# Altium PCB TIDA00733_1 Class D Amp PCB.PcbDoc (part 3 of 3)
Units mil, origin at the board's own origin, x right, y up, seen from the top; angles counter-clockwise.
Board outline 5700 x 4500 mil, 4 copper layers (Top Layer, Signal Layer 1, Signal Layer 2, Bottom Layer), stack 61.668 mil thick; 305 components, 186 nets, 894 pads, 1056 vias.
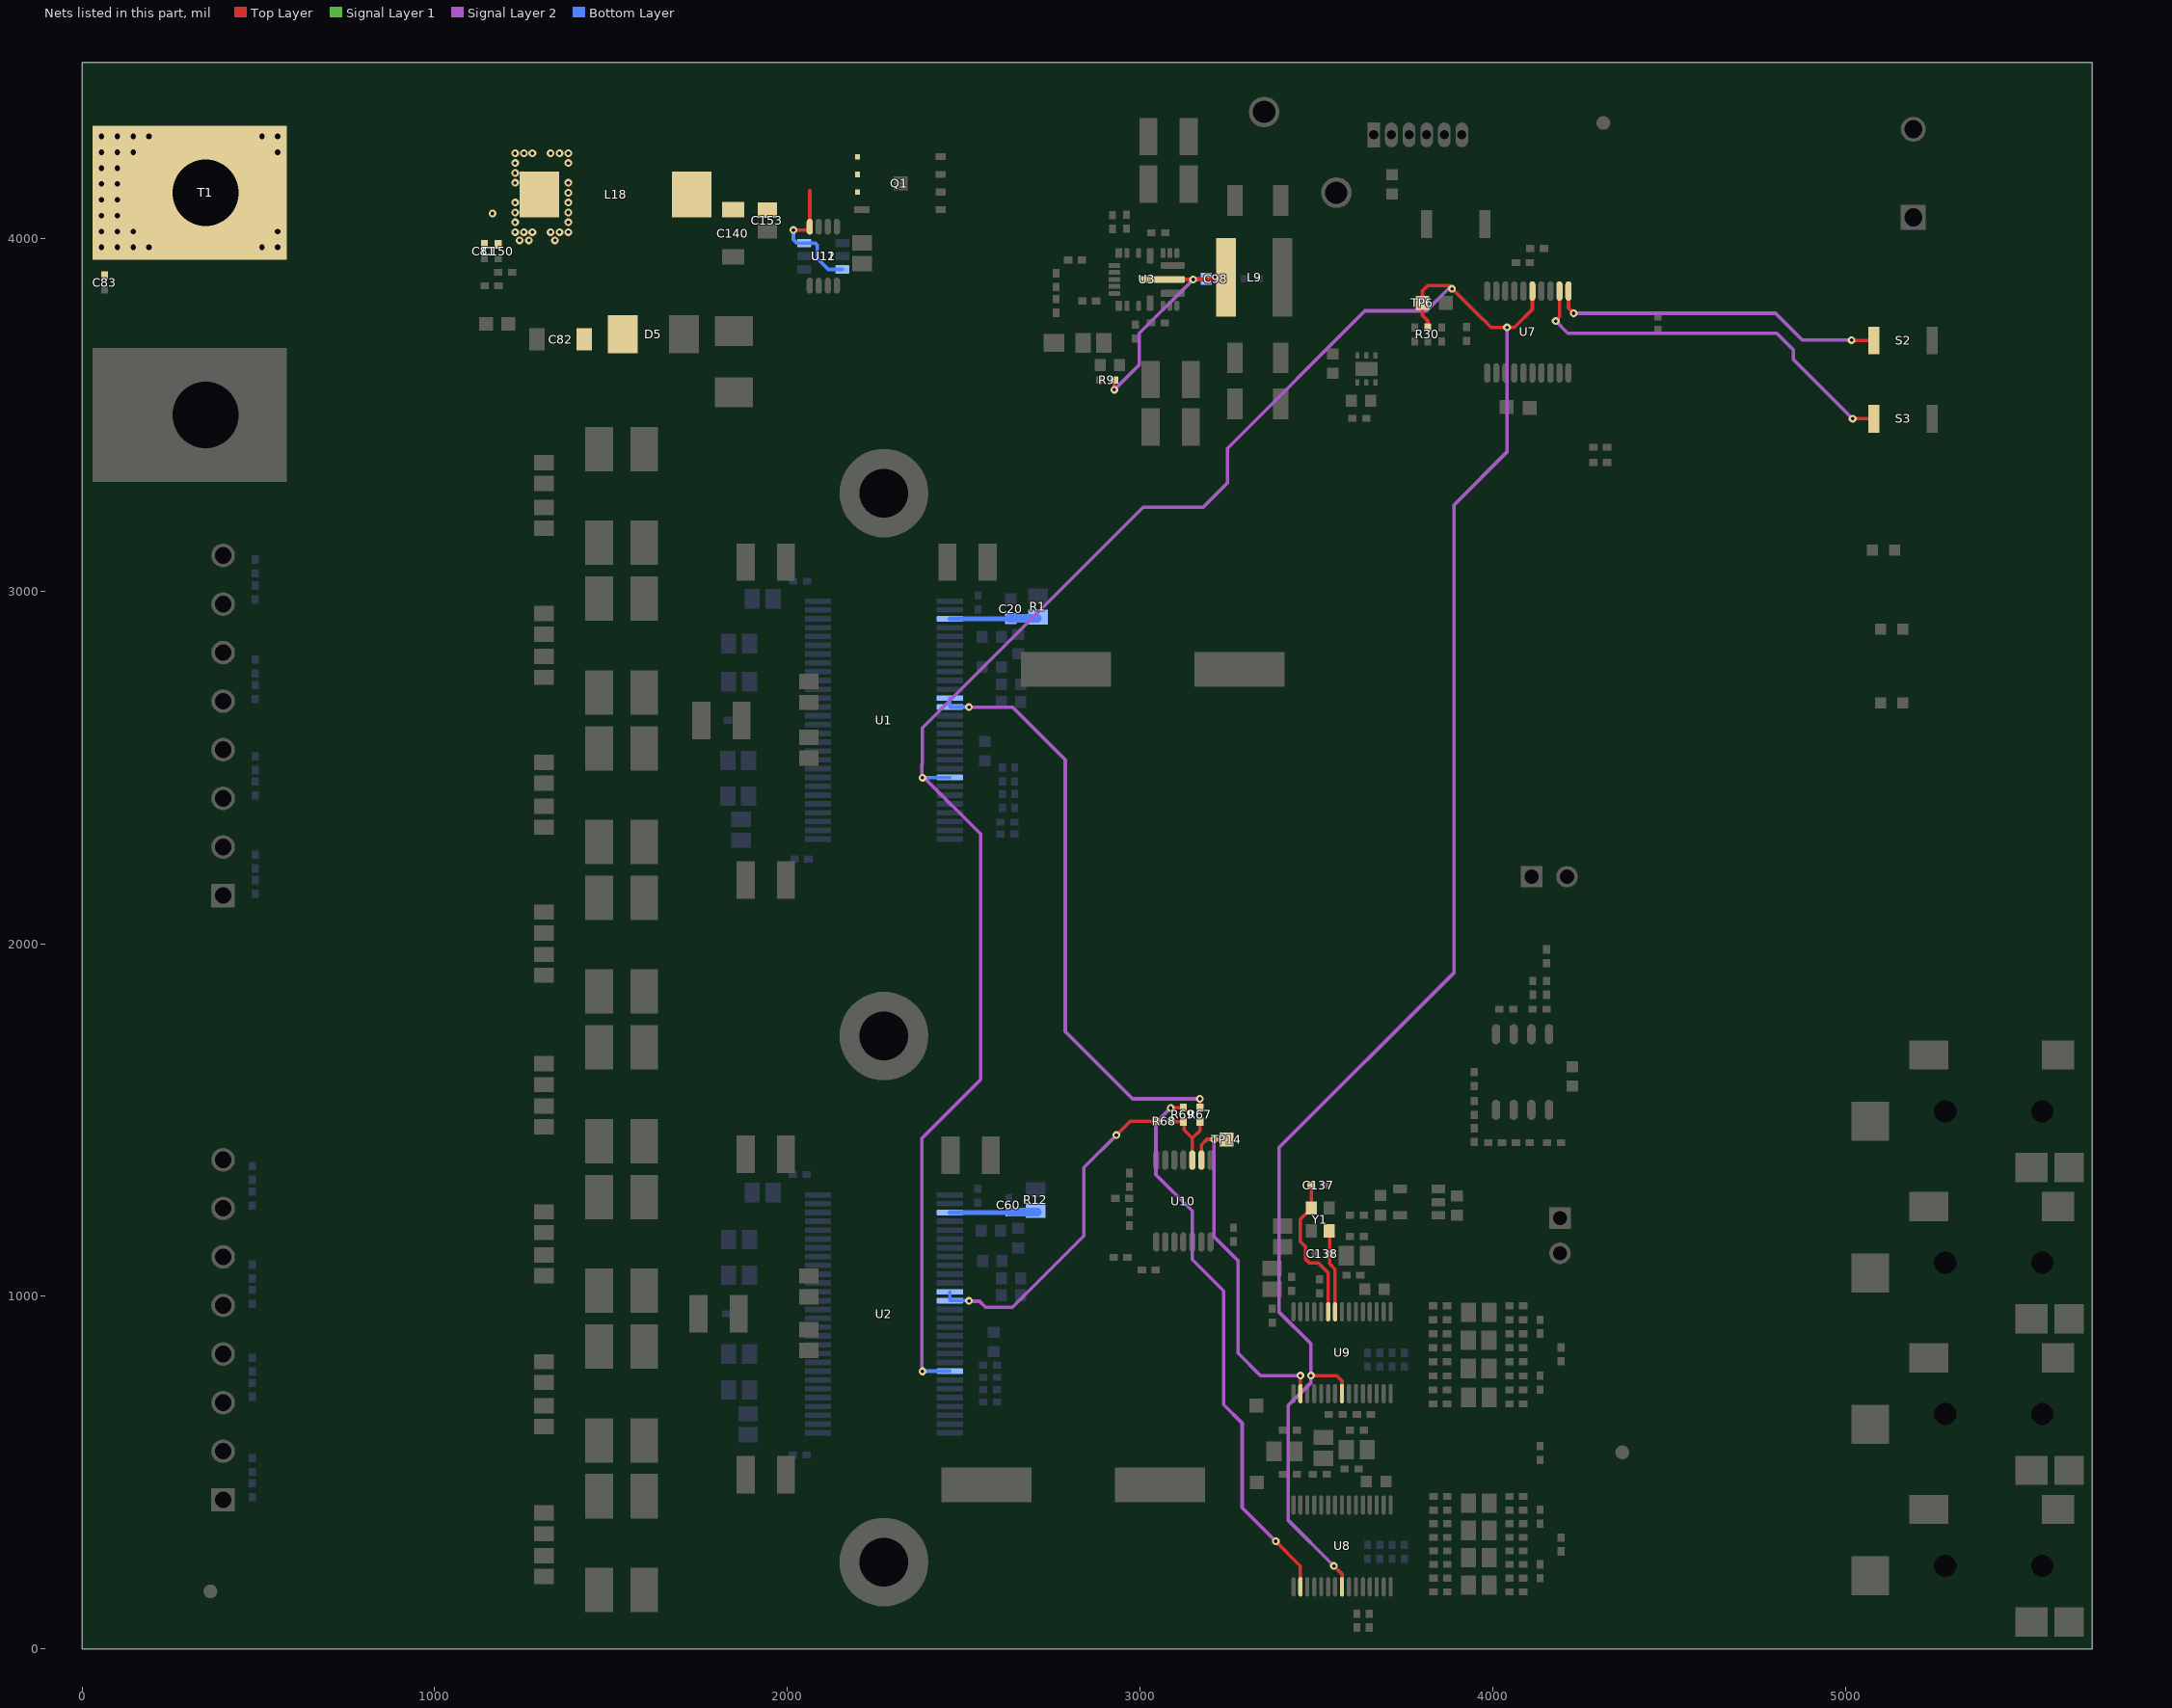
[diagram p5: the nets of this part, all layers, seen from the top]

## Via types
v1: diameter 22, hole 10, Top Layer to Bottom Layer, tented both sides, 975 vias
v2: diameter 32, hole 16, Top Layer to Bottom Layer, tented both sides, 56 vias
v3: diameter 39.37, hole 19.68, Top Layer to Bottom Layer, tented both sides, 18 vias
v4: diameter 26, hole 10, Top Layer to Bottom Layer, 3 vias
v5: diameter 19.68, hole 7.87, Top Layer to Bottom Layer, tented both sides, 2 vias
v6: diameter 26, hole 10, Top Layer to Bottom Layer, tented both sides, 2 vias

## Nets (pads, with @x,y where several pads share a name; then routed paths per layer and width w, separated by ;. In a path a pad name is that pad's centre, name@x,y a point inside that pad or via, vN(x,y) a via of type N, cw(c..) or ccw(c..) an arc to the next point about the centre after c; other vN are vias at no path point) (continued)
SCLK: TP14.1 U9.17 U10.2 | length 999.3
  Top Layer w10: U10.2@3174.18,1386.14 3174.18,1429.18 3190,1445 v1(3210,1445) TP14.1@3235,1445 ; U9.17@3454.89,723.86 3454.89,774.89 v1(3455,775)
  Signal Layer 2 w10: v1(3210,1445) 3210,1169 3278,1101 3278,839 3342,775 v1(3455,775)
SCLK_B1: R67.1 R68.1 R69.1 U10.3 | length 215
  Top Layer w10: R68.1@3084.69,1495 3085,1495.32 3125,1495.32 3125,1472.18 3148.59,1448.59 ; U10.3@3148.59,1386.14 3148.59,1448.59 ; R67.1@3170,1495.32 3170,1470 3148.59,1448.59
SCLK_P2: R69.2 U8.17 | length 1581.6
  Top Layer w10: v1(3087,1534) 3087.69,1534.69 R69.2@3123,1534.69 ; v1(3385,305) 3454.89,235.11 U8.17@3454.89,175.86
  Signal Layer 2 w10: v1(3087,1534) 3045,1492 3045,1345 3148,1242 3148,1104 3237,1015 3237,693 3290,640 3290,400 v1(3385,305)
SCLK_T1: R67.2 U1.12 U1.13 | length 1671.3
  Top Layer w10: R67.2@3170,1534.69 v1(3170,1560)
  Signal Layer 2 w10: v1(2515,2671) 2639,2671 2788,2522 2788,1751 2979,1560 v1(3170,1560)
  Bottom Layer w10: U1.12@2461.01,2696.5 U1.13@2461.01,2671.5 2513.5,2671.5 2514,2671 v1(2515,2671)
SCLK_T2: R68.2 U2.12 U2.13 | length 953.1
  Top Layer w10: v1(2933,1457) 2972,1496 R68.2@3049.31,1496
  Signal Layer 2 w10: v1(2515,987) 2516.2,985.8 2544.86,985.8 2561.86,968.8 2638.8,968.8 2841,1171 2841,1365 v1(2933,1457)
  Bottom Layer w10: U2.12@2461.01,1012.5 U2.13@2461.01,987.5 2514.5,987.5 v1(2515,987)
SDA: R30.1 TP6.1 U1.21 U2.21 U7.15 U8.23 U9.23 | length 8844.4
  Top Layer w10: v1(3485,775) 3558,775 3573,760 U9.23@3573,723.86 ; v1(3550,235) 3573,212 U8.23@3573,175.86 ; R30.1@3816,3747.69 3816,3767 3801,3782 TP6.1@3801,3817 3801,3852 3816,3867 3876.17,3867 v1@3885.26,3857.91 ; v1(3884.83,3857.48) 3889.73,3852.59 v1@3890.59,3852.59 ; v1@3888.17,3855 v1@3890.59,3852.59 ; U7.15@4112.8,3851.14 4112.8,3799 4061.8,3748 v1(4041,3748) 3996,3748 3973,3771 3972.17,3771 v1@3890.59,3852.59
  Signal Layer 2 w10: v1(2383,787) 2381.2,788.8 2381.2,1448.2 2548,1615 2548,2311 v1@2390,2469 ; v1(2383,2471) 2381.2,2472.8 2381.2,2508.66 2383,2510.46 2383,2612 3009,3238 3179,3238 3248,3307 3248,3405 3637.8,3794.8 3811.8,3794.8 3874.48,3857.48 v1(3884.83,3857.48) ; v1(3550,235) 3420,365 3420,690 3485,755 v1(3485,775) 3485,865 3394,956 3394,1421 3891,1918 3891,3245 4040.5,3394.5 v1@4040.5,3748
  Bottom Layer w10: v1(2383,787) 2383.5,787.5 U2.21@2461.01,787.5 ; v1(2383,2471) 2383.5,2471.5 U1.21@2461.01,2471.5
SW_5: C98.1 L9.1 R9.2 U3.9 | length 675.2
  Top Layer w10: R9.2@2926.69,3599 2926.69,3571.31 v1(2927.31,3571.31) ; U3.9@3063.29,3884 v1(3150.9,3884) 3238.5,3884 L9.1@3244.5,3890 L9.1@3259,3904.5
  Signal Layer 2 w10: v1(2927.31,3571.31) 2998,3642 2998,3731.1 v1(3150.9,3884)
  Bottom Layer w10: v1(3150.9,3884) 3152.9,3886 C98.1@3187.44,3886
U1_VBAT: C20.1 R1.2 U1.3 | length 249
  Bottom Layer w10: C20.1@2629.06,2921.5 C20.1@2630,2922.44 ; R1.2@2709.03,2922.44 R1.2@2709.47,2922
  Bottom Layer w13: U1.3@2461.01,2921.5 C20.1@2629.06,2921.5
  Bottom Layer w25: C20.1@2630,2922.44 R1.2@2709.03,2922.44
U2_VBAT: C60.1 R12.2 U2.3 | length 249
  Bottom Layer w10: C60.1@2629.06,1237.5 C60.1@2630,1238.44 ; R12.2@2709.03,1238.44 R12.2@2709.47,1238
  Bottom Layer w13: U2.3@2461.01,1237.5 C60.1@2629.06,1237.5
  Bottom Layer w25: C60.1@2630,1238.44 R12.2@2709.03,1238.44
VBAT: C81.1 C82.1 C83.1 C150.1 D5.1 L18.1 T1.1
  other v1: 1241,3995 1267,3995 1341,3995 1228,4018 1252.5,4018 1277,4018 1328.67,4018 1353.83,4018 1379,4018 1228,4046 1379,4046 1164,4071 1228,4074 1379,4074 1228,4102 1379,4102 1379,4130 1228,4158 1379,4158 1228,4186 1228,4214 1379,4214 1228,4242 1253.17,4242 1277,4242 1328.67,4242 1353.83,4242 1379,4242
  other v2: 55,3975 100,3975 145,3975 190,3975 510,3975 555,3975 55,4020 100,4020 145,4020 555,4020 55,4065 100,4065 55,4110 100,4110 55,4155 100,4155 55,4200 100,4200 55,4245 100,4245 145,4245 555,4245 55,4290 100,4290 145,4290 190,4290 510,4290 555,4290
VIN_FLT: C140.1 C153.1 L18.2 Q1.1 Q1.2 Q1.3 U11.4 U12.3 U12.6 | length 376.1
  Top Layer w10: v1(2017,4024) 2053.95,4024 U11.4@2063.61,4033.66 2063.61,4136.39
  Bottom Layer w10: v1(2017,4024) 2017,3997 2026.6,3987.4 U12.3@2047.87,3987.4 2078.6,3987.4 2085,3981 2085,3944 2116.4,3912.6 U12.6@2156.13,3912.6
VOL_DN: S3.1 U7.12 | length 1122.4
  Top Layer w10: v1(4179,3766) 4179,3767 4189.57,3777.57 U7.12@4189.57,3851.14 ; v1(5021,3489) S3.1@5081.32,3489
  Signal Layer 2 w10: v1(4179,3766) 4213.5,3731.5 4805.5,3731.5 4853,3684 4853,3657 v1(5021,3489)
VOL_UP: S2.1 U7.11 | length 960
  Top Layer w10: U7.11@4215.16,3851.14 4215.16,3802.84 v1(4230,3788) ; v1(5018,3712) 5019,3711 S2.1@5081.32,3711
  Signal Layer 2 w10: v1(4230,3788) 4802,3788 4878,3712 v1(5018,3712)
  Signal Layer 1 w10: v1@4230,3780.51 v1(4230,3788)
XI: C137.1 U9.10 Y1.1 | length 419.1
  Top Layer w10: C137.1@3486.32,1315 3486.32,1250.56 3486.4,1250.48 3455,1219.08 3455,1155 3470,1140 3470,1105 3480,1095 3505,1095 3533.63,1066.37 U9.10@3533.63,956.14
XO: C138.1 U9.9 Y1.3 | length 236.7
  Top Layer w10: Y1.3@3535.61,1185.52 3537.69,1183.44 C138.1@3537.69,1120 3537.69,1092.32 3553.31,1076.68 U9.9@3553.31,956.14
pads on no net: FID1.1 FID2.1 FID3.1 J5.1 J5.6 J6.4 J6.5 J6.MH1 J6.MH2 J7.4 J7.5 J7.MH1 J7.MH2 J8.4 J8.5 J8.MH1 J8.MH2 J9.4 J9.5 J9.MH1 J9.MH2 U3.4A U3.4B U3.8A U3.8B U3.9A U3.9B U3.9C U3.9D U3.10A U3.10B U3.14A U3.14B U3.17 U5.4 U6.3 U6.7@3624.28,3630 U6.7@3659.72,3630 U7.2 U7.3 U7.7 U7.10 U7.13 U7.18 U7.19 U8.5 U8.9 U8.10 U8.15 U8.19 U8.20 U8.21 U8.22 U9.5 U9.15 U9.19 U9.20 U9.21 U9.22 U10.11 U11.3 U11.5

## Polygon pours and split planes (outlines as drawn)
PVDD on Top Layer "TOP_LAYER_PVDD_P280" (solid, remove dead copper, pour order 280): 2233,646 2276,603 2363,603 2419,547 2727,547 2727,381 2376,381 2324,433 2151,433 1967,433 1967,528 2051,612 2051,764 2100,813 2100,1123 2014,1210.19 2014,2410.26 2098.56,2494.82 2098.56,2775.18 2014,2859.74 2014,3652.62 2080,3710.97 2489,3710.97 2489,3500 2201,3500 2148,3447 2148,2933 2170,2911 2423,2911 2540,2911 2543,2914 2543,3031 2609,3031 2609,2883 2630,2862 2918,2862 2918,2696 2401,2696 2307,2602 2307,2423 2151,2267 2151,2126 2151,1381 2188,1344 2596,1344 2596,1341 2612,1325 2610,1323 2610,1243 2604,1237 2295,1237 2289,1237 2233,1181
GND on Top Layer "Top GND" (solid, remove dead copper, pour order 326): 25,4475 5675,4475 5675,25 25,25
SW_5 on Top Layer "Top Layer-No Net" (solid, remove dead copper, pour order 204): 3066,3894 3121,3894 3131,3904 3151,3924 3151,3939 3151,3959 3186,3994 3196,4004 3216,4004 3271,4004 3271,3779 3211,3779 3196,3779 3161,3814 3151,3824 3151,3844 3141,3854 3121,3874 3111,3874 3066,3874
PVDD on Top Layer "Top Layer-No Net" (solid, remove dead copper, pour order 206): 2272,4243.81 2371.19,4343 2472,4345 3051,4345 3051,3874 3051,3406 2643,3406 2549,3500 2272,3500
VBAT on Top Layer "Top Layer-No Net" (solid, remove dead copper, pour order 205): 1412,4096 1573,3935 1573,3678 1571,3676 1570,3677 1399,3677 1399,3733 1399,3946 1373,3972 1132,3972 1132,4322 1412,4322 1412,4182
PVDD on Top Layer "Top Layer-No Net" (solid, remove dead copper, pour order 200): 1909,1001 1929,981 1944,966 1954,966 1964,966 2110,966 2110,936 1944,936 1909,896 1878,896 1878,1001
PVDD on Top Layer "Top Layer-No Net" (solid, remove dead copper, pour order 259): 1894,2685 1929,2650 1954,2650 1964,2650 2112,2650 2112,2620 1927.75,2620 1892.75,2580 1878,2580 1878,2685
OUT8+ on Signal Layer 1 "SIGNAL_LAYER_1_OUT8+_P284" (solid, remove dead copper, pour order 284): 1204,3472 1004,3472 689,3157 352,3157 352,3032 862,3032 1172,3342 1204,3342 1208,3346 1208,3471
OUTCP on Signal Layer 1 "Top Layer-No Net" (solid, remove dead copper, pour order 225): 1633.58,933.9 1633.58,773.9 1650.3,757.18 1826.87,757.18 1933.58,863.9 1958.58,863.9 1993.58,863.9 1993.58,915.18 1864.87,915.18 1822.87,873.18 1724.3,873.18 1663.58,933.9
OUT3P2 on Signal Layer 1 "Top Layer-No Net" (solid, remove dead copper, pour order 227): 1601,1357 1676,1357 1686,1357 1686,1252 1741,1197 1809.72,1128.28 1889,1128.28 1933,1084.28 1993,1084.28 1993,1037 1946,1037 1796,1037 1726,1037 1631,1132 1601,1162 1601,1182
OUT4P2 on Signal Layer 1 "Top Layer-No Net" (solid, remove dead copper, pour order 231): 1633,1772.74 1633,1642.74 1633,1592.74 1658,1567.74 1693,1532.74 1693,1317.74 1820.72,1190.03 1993,1190.03 1993,1247.74 1988,1252.74 1933,1252.74 1848,1337.74 1815.5,1370.24 1815.5,1410.24 1815.5,1642.74 1688,1772.74
OUTSP on Signal Layer 1 "Top Layer-No Net" (solid, remove dead copper, pour order 229): 1629,361.48 1744.02,361.48 1837.75,455.22 1837.75,534.25 1909,605.5 1909,678.5 1940.72,710.22 1994,710.22 1994,775.22 1954,775.22 1899,775.22 1731,607.22 1731,559.72 1663.39,492.11 1629,492.11
OUT1P on Signal Layer 1 "Top Layer-No Net" (solid, remove dead copper, pour order 228): 1632,2060.5 1667,2060.5 1712,2060.5 1760.75,2060.5 1840.75,2140.5 1840.75,2221.75 1897,2278 1912,2293 1912,2360.5 1947,2395.5 1997,2395.5 1997,2460.5 1957,2460.5 1887,2460.5 1882,2455.5 1822,2395.5 1719.5,2293 1719.5,2278 1719.5,2230.5 1679.5,2190.5 1632,2190.5
OUT4P on Signal Layer 1 "Top Layer-No Net" (solid, remove dead copper, pour order 230): 1638,3464 1638,3334 1638,3284 1663,3259 1698,3224 1698,3009 1833,2874 1998,2874 1998,2939 1993,2944 1938,2944 1853,3029 1820.5,3061.5 1820.5,3101.5 1820.5,3334 1693,3464
OUT3P on Signal Layer 1 "Top Layer-No Net" (solid, remove dead copper, pour order 226): 1603,3042 1678,3042 1688,3042 1688,2937 1743,2882 1808,2817 1893,2817 1908,2817 1933,2792 1943,2792 1963,2792 1998,2792 1998,2722 1948,2722 1798,2722 1728,2722 1633,2817 1603,2847 1603,2867
OUT2P on Signal Layer 1 "Top Layer-No Net" (solid, remove dead copper, pour order 224): 1633,2616 1633,2456 1683,2406 1733,2406 1808,2406 1923,2521 1948,2546 1958,2546 1998,2546 1998,2591 1998,2611 1943,2611 1898,2611 1878,2611 1808,2541 1793,2541 1738,2541 1663,2616
OUT7+ on Signal Layer 1 "SIGNAL_LAYER_1_OUT7+_P286" (solid, remove dead copper, pour order 286): 1208.67,3046.46 978.67,3046.46 808.08,2875.87 353.67,2875.87 353.67,2757.87 1046.87,2757.87 1208.67,2919.67
OUT5+ on Signal Layer 1 "SIGNAL_LAYER_1_OUT5+_P302" (solid, remove dead copper, pour order 302): 1200.23,2065 1200.23,2195 846,2195 703,2338 352,2338 352,2201 571.79,2201 707.8,2065
OUT6+ on Signal Layer 1 "SIGNAL_LAYER_1_OUT6+_P304" (solid, remove dead copper, pour order 304): 351.82,2476.59 351.82,2613 898,2613 905,2620 1200,2620 1200,2490 1186,2476 1159,2449 599.39,2449 571.79,2476.59
OUT2+ on Signal Layer 1 "SIGNAL_LAYER_1_OUT2+_P318" (solid, remove dead copper, pour order 318): 351.82,762.59 351.82,899 898,899 924,925 1200,925 1200,794 1141,735 599.39,735 571.79,762.59
OUT1+ on Signal Layer 1 "SIGNAL_LAYER_1_OUT1+_P320" (solid, remove dead copper, pour order 320): 1200.23,365 1200.23,500 827,500 703,624 352,624 352,487 571.79,487 693.79,365
OUT3+ on Signal Layer 1 "SIGNAL_LAYER_1_OUT3+_P322" (solid, remove dead copper, pour order 322): 1208.67,1345 991.21,1345 808.08,1161.87 353.67,1161.87 353.67,1043.87 1038.87,1043.87 1208.67,1213.67
OUT4+ on Signal Layer 1 "SIGNAL_LAYER_1_OUT4+_P324" (solid, remove dead copper, pour order 324): 1204,1758 1004,1758 689,1443 352,1443 352,1318 862,1318 1172,1628 1204,1628 1208,1632 1208,1757
GND on Signal Layer 1 "Sig 1 GND" (solid, remove dead copper, pour order 334): 25,4475 5675,4475 5675,25 25,25
+5V on Signal Layer 2 "Top Layer-No Net" (solid, remove dead copper, pour order 240): 3429,4200 5245,4200 5245,3990 5245,3963 3429,3963
OUT8- on Signal Layer 2 "SIGNAL_LAYER_2_OUT8-_P282" (solid, remove dead copper, pour order 282): 1206,3072 1206,3200 1202,3204 739,3204 567,3032 353,3032 353,2903 486,2903 732,2903 899,3070 1201,3070
OUTCM on Signal Layer 2 "Top Layer-No Net" (solid, remove dead copper, pour order 210): 1629,666.5 1629,686.5 1629,711.5 1679,761.5 1714,796.5 1779,861.5 1814,861.5 1994,861.5 1994,816.5 1994,801.5 1974,781.5 1869,781.5 1824,736.5 1709,621.5 1709,551.5 1679,521.5 1629,521.5
OUT3M2 on Signal Layer 2 "Top Layer-No Net" (solid, remove dead copper, pour order 208): 1622.71,1066.64 1691.71,1135.64 1816.71,1135.64 1920.71,1031.64 1992.71,1031.64 1992.71,982.64 1854.71,982.64 1811.71,1025.64 1738.71,1025.64 1667.71,954.64 1622.71,954.64
OUT4M2 on Signal Layer 2 "Top Layer-No Net" (solid, remove dead copper, pour order 211): 1633,1517.72 1668,1517.72 1713,1517.72 1798,1432.72 1798,1397.72 1838,1357.72 1903,1292.72 1908,1287.72 1908,1207.72 1929.72,1186 1993,1186 1993,1132 1873.72,1132 1823,1182.72 1823,1197.72 1693,1327.72 1644.72,1376 1633,1376
OUTSM on Signal Layer 2 "Top Layer-No Net" (solid, remove dead copper, pour order 214): 1634,101.89 1634,236 1694,296 1694,349.89 1731.5,387.39 1731.5,611.78 1824.72,705 1994,705 1994,640 1989,635 1934,635 1840,541 1840,268.5 1816.5,245 1673.39,101.89
OUT1M on Signal Layer 2 "Top Layer-No Net" (solid, remove dead copper, pour order 213): 1637,1799 1637,1929 1637,1979 1662,2004 1697,2039 1697,2191.5 1734.5,2229 1734.5,2291.5 1832,2389 1997,2389 1997,2324 1992,2319 1937,2319 1852,2234 1852,2174 1819.5,2141.5 1819.5,1929 1692,1799
OUT4M on Signal Layer 2 "Top Layer-No Net" (solid, remove dead copper, pour order 212): 1638,3202 1673,3202 1718,3202 1803,3117 1803,3082 1843,3042 1908,2977 1913,2972 1913,2892 1938,2867 1998,2867 1998,2802 1963,2802 1893,2802 1888,2807 1828,2867 1828,2882 1698,3012 1698,3037 1668,3067 1638,3067
OUT3M on Signal Layer 2 "Top Layer-No Net" (solid, remove dead copper, pour order 207): 1628,2777.5 1678,2827.5 1693,2827.5 1768,2827.5 1838,2827.5 1848,2817.5 1948,2717.5 1968,2717.5 1998,2717.5 1998,2657.5 1998,2652.5 1943,2652.5 1933,2652.5 1898,2652.5 1873,2677.5 1823,2727.5 1738,2727.5 1723,2712.5 1658,2647.5 1628,2647.5
OUT2M on Signal Layer 2 "Top Layer-No Net" (solid, remove dead copper, pour order 209): 1632,2349.5 1632,2369.5 1632,2394.5 1682,2444.5 1717,2479.5 1782,2544.5 1817,2544.5 1997,2544.5 1997,2499.5 1997,2484.5 1977,2464.5 1872,2464.5 1827,2419.5 1712,2304.5 1712,2234.5 1692,2214.5 1632,2214.5
+3P3V on Signal Layer 2 "SIGNAL_LAYER_2_+3P3V_P278" (solid, remove dead copper, pour order 278): 3813,3376 3910,3473 3910,3581 3910,3725 3749.62,3725 3749.62,3522 3677,3522 3652,3497 3652,3429 3705,3376
OUT7- on Signal Layer 2 "SIGNAL_LAYER_2_OUT7-_P288" (solid, remove dead copper, pour order 288): 1206,2650 1206,2781 591.59,2781 567,2756.41 353,2756.41 353,2627.41 486,2627.41 884.41,2627.41 907,2650
OUT5- on Signal Layer 2 "SIGNAL_LAYER_2_OUT5-_P294" (solid, remove dead copper, pour order 294): 1201.23,1630.77 1200.23,1631.77 1200.23,1928.77 1083.23,1928.77 806,2206 352,2206 352,2071 689,2071 961.23,1798.77 1201.23,1798.77
OUT4- on Signal Layer 2 "SIGNAL_LAYER_2_OUT4-_P296" (solid, remove dead copper, pour order 296): 1206,1375 1206,1508 755,1508 567,1320 353,1320 353,1191 486,1191 732,1191 916,1375
OUT6- on Signal Layer 2 "SIGNAL_LAYER_2_OUT6-_P292" (solid, remove dead copper, pour order 292): 352,2342 352,2478 861,2478 984,2355 1200,2355 1200,2224 1067,2224 831,2224 713,2342
OUT2- on Signal Layer 2 "SIGNAL_LAYER_2_OUT2-_P308" (solid, remove dead copper, pour order 308): 352,628 352,764 861,764 970,655 1200,655 1200,525 806,525 703,628
OUT1- on Signal Layer 2 "SIGNAL_LAYER_2_OUT1-_P310" (solid, remove dead copper, pour order 310): 1200.23,100 1200.23,231 1097,231 836,492 352,492 352,357 701,357 957.27,100
OUT3- on Signal Layer 2 "SIGNAL_LAYER_2_OUT3-_P314" (solid, remove dead copper, pour order 314): 1206,949 1206,1080 604.59,1080 567,1042.41 353,1042.41 353,913.41 486,913.41 884.41,913.41 920,949
GND on Signal Layer 2 "Sig 2 GND" (solid, remove dead copper, pour order 330): 25,4475 5675,4475 5675,25 25,25
OUT1M on Bottom Layer "Top Layer-No Net" (solid, remove dead copper, pour order 276): 2035,2390 1935,2390 1913,2368 1913,2333 1921,2325 1945,2325 1965,2325 1990,2350 2005,2365 2035,2365 2090,2365 2090,2380 2045,2380
OUT1P on Bottom Layer "Top Layer-No Net" (solid, remove dead copper, pour order 274): 2090,2415 2090,2410 2045,2410 2035,2400 2015,2400 1912,2400 1907,2405 1907,2439 1912,2444 1986,2444 2000,2430 2010,2430 2090,2430
OUT2P on Bottom Layer "Top Layer-No Net" (solid, remove dead copper, pour order 272): 2090,2565 2090,2560 2045,2560 2035,2550 1930,2550 1907,2573 1907,2592 1915,2600 1971,2600 1991,2580 2010,2580 2090,2580
OUT2M on Bottom Layer "Top Layer-No Net" (solid, remove dead copper, pour order 270): 2034,2541 1912,2541 1906,2535 1906,2498 1908,2496 1978,2496 1997,2515 2035,2515 2090,2515 2090,2530 2045,2530
GND on Bottom Layer "Bottom Layer GND" (solid, remove dead copper, pour order 332): 25,4475 5675,4475 5675,25 25,25
OUTCM on Bottom Layer "Top Layer-No Net" (solid, remove dead copper, pour order 248): 2034,857 1912,857 1906,851 1906,814 1908,812 1978,812 1997,831 2035,831 2090,831 2090,846 2045,846
OUTCP on Bottom Layer "Top Layer-No Net" (solid, remove dead copper, pour order 256): 2090,881 2090,876 2045,876 2035,866 1930,866 1907,889 1907,908 1915,916 1971,916 1991,896 2010,896 2090,896
OUT3P2 on Bottom Layer "Top Layer-No Net" (solid, remove dead copper, pour order 255): 2090,1056 2090,1051 2045,1051 2031,1037 1899,1037 1899,1087 1984,1087 2000,1071 2010,1071 2090,1071
OUT3M2 on Bottom Layer "Top Layer-No Net" (solid, remove dead copper, pour order 243): 2038,1028 1926,1028 1920,1022 1920,1001 1938,983 1982,983 1990,991 2005,1006 2035,1006 2090,1006 2090,1021 2045,1021
OUT4M2 on Bottom Layer "Top Layer-No Net" (solid, remove dead copper, pour order 250): 2032,1184 1899,1184 1899,1134 1983,1134 1990,1141 2005,1156 2035,1156 2090,1156 2090,1171 2045,1171
OUT4P2 on Bottom Layer "Top Layer-No Net" (solid, remove dead copper, pour order 258): 2090,1206 2090,1201 2045,1201 2039,1195 1942,1195 1894,1243 1894,1277 1922,1277 1922,1258 1937.01,1243 1981,1243 2003,1221 2010,1221 2090,1221
OUTSP on Bottom Layer "Top Layer-No Net" (solid, remove dead copper, pour order 254): 2090,731 2090,726 2045,726 2035,716 2015,716 1912,716 1907,721 1907,755 1912,760 1986,760 2000,746 2010,746 2090,746
OUTSM on Bottom Layer "Top Layer-No Net" (solid, remove dead copper, pour order 244): 2035,706 1935,706 1913,684 1913,649 1921,641 1945,641 1965,641 1990,666 2005,681 2035,681 2090,681 2090,696 2045,696
OUT4P on Bottom Layer "OUT4P" (solid, remove dead copper, pour order 262): 2090,2890 2090,2885 2045,2885 2039,2879 1942,2879 1894,2927 1894,2961 1922,2961 1922,2942 1937.01,2927 1981,2927 2003,2905 2010,2905 2090,2905
OUT4M on Bottom Layer "OUT4M" (solid, remove dead copper, pour order 264): 2032,2868 1899,2868 1899,2818 1983,2818 1990,2825 2005,2840 2035,2840 2090,2840 2090,2855 2045,2855
OUT3M on Bottom Layer "PUT3M" (solid, remove dead copper, pour order 266): 2038,2712 1926,2712 1920,2706 1920,2685 1938,2667 1982,2667 1990,2675 2005,2690 2035,2690 2090,2690 2090,2705 2045,2705
OUT3P on Bottom Layer "OUT3P" (solid, remove dead copper, pour order 268): 2090,2740 2090,2735 2045,2735 2031,2721 1899,2721 1899,2771 1984,2771 2000,2755 2010,2755 2090,2755

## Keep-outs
Keep-Out Layer:
  text ".Layer_Name" at 7,-1458.49 h60

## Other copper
Top Layer:
  rectangle net GND: 2438,1348 2522,1452
  region net AGND: 2771,3732 2771,3677 2854,3677 2854,3732
  rectangle net OUT1-: 1170,100 1505,230
  rectangle net OUT1+: 1170,363 1505,498
  rectangle net OUT2-: 1170,527 1505,657
  rectangle net OUT2+: 1170,792 1505,922
  rectangle net OUT3-: 1170,952 1505,1082
  rectangle net OUT3+: 1170,1215 1505,1345
  rectangle net OUT4-: 1170,1375 1505,1505
  rectangle net OUT4+: 1170,1638 1505,1773
  rectangle net OUT5-: 1170,1803 1505,1933
  rectangle net OUT5+: 1170,2065 1505,2195
  rectangle net OUTSM: 1555,100 1665,235
  rectangle net OUTSP: 1555,365 1665,495
  rectangle net OUTCM: 1555,525 1665,655
  rectangle net OUTCP: 1555,790 1665,920
  rectangle net OUT3M2: 1555,950 1665,1080
  rectangle net OUT3P2: 1555,1212 1665,1347
  rectangle net OUT4M2: 1555,1377 1665,1507
  rectangle net OUT4P2: 1555,1640 1665,1770
  rectangle net OUT1M: 1555,1799 1665,1934
  rectangle net OUT1P: 1555,2060 1665,2195
  rectangle net PVDD: 1970,446 2125,546
  rectangle net PVDD: 2545,1251 2610,1485
  rectangle net PVDD: 1970,1346 2125,1451
  rectangle net OUT8+: 1170,3340 1500,3466
  rectangle net OUT8-: 1170,3072 1505,3202
  region net NetD5_2: 1641,3820 1641,3625 1931,3625 1931,3820
  rectangle net OUT7+: 1170,2912 1505,3042
  rectangle net OUT7-: 1170,2650 1505,2780
  rectangle net OUT6+: 1170,2490 1505,2620
  rectangle net OUT6-: 1170,2225 1505,2355
  rectangle net OUT4P: 1555,3339 1665,3466
  rectangle net OUT4M: 1555,3072 1665,3202
  rectangle net OUT3P: 1555,2906 1665,3041
  rectangle net OUT3M: 1555,2648 1665,2778
  rectangle net OUT2P: 1555,2483 1665,2618
  rectangle net OUT2M: 1555,2224 1665,2359
  rectangle net PVDD: 1970,3030 2125,3135
  rectangle net PVDD: 2545,2935 2610,3165
  rectangle net PVDD: 1970,2128 2125,2234
  region net +5V: 3346,4156 3346,3344 3501,3344 3501,4156
  region net +3P3V: 3707,3500 3632,3500 3632,3475 3707,3475
  region net GND: 2700.86,3734 2700.86,3673.86 2746,3673.86 2746,3734
  rectangle net GND: 2381,3027 2479.31,3134.95
  region net VIN_FLT: 2001,4059 2001,4011 2072,4011 2072,4058 2072,4107.03 2240,4106.98 2240,4272 1993,4272 1992,4271 1668,4271 1668,4059
  pour cut-out: 2951,3829 2951,4049 2886,4049 2811,3974 2811,3934 2779.59,3903.84 2779.59,3725.41 2811,3694 2986,3694 2992.23,3700.23 2992.23,3829.05
  pour cut-out: 2778.76,3857 2779,3663.66 2768.21,3663.66 2712,3663.66 2712,3857
  region net AGND: 2848,3880 2838,3890 2811,3890 2786,3865 2786,3732 2771,3732 2771,3676 2848,3676
  region net VBAT: 213,3882 45,3882 45,3955 211,3955
  text ".Layer_Name" at 7,-1458.49 h60
Signal Layer 2:
  rectangle net +5V: 3435.86,3340 3494,3439.14
  region net VBAT: 30,3940 598,3940 1411,3940 1411,4323 30,4323
  text ".Layer_Name" at 7,-1458.49 h60
Signal Layer 1:
  region net VBAT: 30,3940 598,3940 1411,3940 1411,4323 30,4323
  text ".Layer_Name" at 7,-1458.49 h60
Bottom Layer:
  rectangle net PVDD: 2560,1252 2605,1485
  rectangle net PVDD: 2030,929 2121,971
  rectangle net PVDD: 2560,2936 2609,3165
  rectangle net PVDD: 2040,446 2135,646
  rectangle net PVDD: 2530,1252 2600,1280
  rectangle net PVDD: 2040,1256 2135,1451
  rectangle net PVDD: 2040,2940 2135,3135
  rectangle net PVDD: 2530,2936 2600,2965
  rectangle net PVDD: 2045,2130 2135,2330
  rectangle net PVDD: 2030,2613 2121,2655
  rectangle net +5V: 3434.32,3342 3496,3440.16
  text ".Layer_Name" at 7,-1458.49 h60

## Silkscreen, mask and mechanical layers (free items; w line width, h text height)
Top Overlay:
  lines w10: 1080,0 1080,4500 ; 3797,688 3808,699 ; 4269,1673 4286,1690 4288,1690 4300,1690 ; 4500,0 4500,4500
  text "'.PRJ_Number'  .PCB_Rev-" at 2306,4329 h108.27
  text "POWER INPUT" at 690,4311 h160 r270
  text "-" at 5585,4294 h160 r90
  text "+" at 588,4173 h160 r270
  text "+" at 5604,3999 h160 r90
  text "+5V, 3A OUTPUT" at 5651,3867 h80 r90
  text "SDA" at 3820,3851 h50 r90
  text "SCL" at 3879,3846 h50 r90
  text "-" at 609,3471 h160 r270
  text "+" at 228,3067.77 h160 r90
  text "8" at 148,3047.77 h100 r270
  text "POWER" at 5257.7,3016.7 h60 r90
  text "-" at 213,2937.77 h160 r90
  text "WARN" at 5257,2810.7 h60 r90
  text "+" at 228,2792.18 h160 r90
  text "7" at 148,2772.18 h100 r270
  text "-" at 213,2662.18 h160 r90
  text "FAULT" at 5257,2597.52 h60 r90
  text "+" at 228,2516.59 h160 r90
  text "6" at 148,2496.59 h100 r270
  text "-" at 213,2386.59 h160 r90
  text "+" at 228,2241 h160 r90
  text "5" at 148,2221 h100 r270
  text "-" at 213,2111 h160 r90
  text "OUTPUTS" at 286,1955 h100 r270
  text "IN3, 4" at 5055,1585 h80 r90
  text "SCLK" at 3280,1415 h50
  text "+" at 221,1344.77 h160 r90
  text "4" at 141,1324.77 h100 r270
  text "-" at 206,1214.77 h160 r90
  text "IN1, 2" at 5055,1145 h80 r90
  text "+" at 221,1069.18 h160 r90
  text "3" at 141,1049.18 h100 r270
  text "-" at 206,939.18 h160 r90
  text "+" at 221,793.59 h160 r90
  text "2" at 141,773.59 h100 r270
  text "IN7, 8" at 5055,725 h80 r90
  text "-" at 206,663.59 h160 r90
  text "LRCLK" at 3293,624 h50 r90
  text "+" at 221,518 h160 r90
  text "1" at 141,498 h100 r270
  text "-" at 206,388 h160 r90
  text "DOUT" at 3315,325 h50 r90
  text "IN5, 6" at 5055,290 h80 r90
  text ".Layer_Name" at 7,-1458.49 h60
Bottom Overlay:
  lines w10: 1080,0 1080,4500 ; 4500,0 4500,4500
  text ".Layer_Name" at 7,-1458.49 h60
Top Paste:
  text ".Layer_Name" at 7,-1458.49 h60
Bottom Paste:
  text ".Layer_Name" at 7,-1458.49 h60
Top Solder:
  rectangle: 830,0 1070,4500
  rectangle: 4510,0 4742,4500
  text ".Layer_Name" at 7,-1458.49 h60
  text ".Layer_Name" at 7,-1458.49 h60
Bottom Solder:
  rectangle: 830,0 1070,4500
  rectangle: 4510,0 4741,4500
  text ".Layer_Name" at 7,-1458.49 h60
Drill Guide:
  text ".Layer_Name" at 7,-1458.49 h60
M1 Board Outline:
  the board outline again, w10
  text ".Layer_Name" at 7,-1458.49 h60
M2 Board Dimensions:
  rectangle: -220,-875 -95,-750
  rectangle: -95,-1000 280,-875
  lines w7: -220,-875 780,-875 ; -95,-1000 -95,-750 ; 30,-1000 30,-750 ; 280,-1000 280,-750 ; 530,-1000 530,-750 ; -220,-1000 780,-1000 780,-750 -220,-750 -220,-1000
  text ".Layer_Name" at 7,-1458.49 h60
M3 3D STEP Top:
  text ".Layer_Name" at 7,-1458.49 h60
M4 3D STEP Bottom:
  text ".Layer_Name" at 7,-1458.49 h60
M5 Assembly Top:
  lines w10: -862,-1530.17 5738,-1530.17 ; -862,-1326.83 5740,-1326.83 ; -862,-1123.5 -862,-1733.5 3143,-1733.5 5740,-1733.5 5740,-1123.5 -861.5,-1123.5 -861.5,-1733.5 714,-1733.5 ; 1603,-1733.5 1603,-1123.5 ; 2870,-1326.83 2870,-1123.5 ; 3710,-1326.83 3710,-1123.5 ; 4332,-1740 4332,-1537.17
  text "COMPONENTS MARKED 'DNP' SHOULD NOT BE POPULATED." at 583.5,-918.5 h60
  text "ASSEMBLY VARIANT:" at 583,-1034 h60
  text ".VariantName" at 1619,-1034 h60
  text "PCB VIEWED FROM TOP SIDE" at -798.5,-1255.67 h60
  text "BOARD #:" at 1678,-1255.67 h60
  text ".PRJ_Number" at 2223.5,-1255.67 h60
  text "REV:" at 3068,-1255.67 h60
  text ".PCB_Rev" at 3359.5,-1255.67 h60
  text "SVN REV:" at 3906,-1255.67 h60
  text ".VersionControl_RevNumber" at 4412,-1255.67 h60
  text "TID #:" at 1678,-1459 h60
  text ".TID" at 2223.5,-1459 h60
  text "PLOT NAME =" at -798.5,-1664.34 h60
  text ".plot_File_Name" at 7,-1664.34 h60
  text "GENERATED    :" at 1680,-1664.34 h60
  text ".Print_Date" at 2549.5,-1664.34 h60
  text ".Print_Time" at 3278.5,-1664.34 h60
  text "TEXAS INSTRUMENTS" at 4543,-1664.34 h60
M6 Assembly Bottom:
  lines w10: -862.5,-1327.33 5739.5,-1327.33 ; -860.5,-1530.67 5739.5,-1530.67 ; 545.5,-1740.5 545.5,-1537.67 ; 1167.5,-1327.33 1167.5,-1124 ; 2007.5,-1327.33 2007.5,-1124 ; 3274.5,-1734 3274.5,-1124 ; 4163.5,-1734 5739,-1734 5739,-1124 -862.5,-1124 -862.5,-1734 1734.5,-1734 5739.5,-1734 5739.5,-1124
  text "COMPONENTS MARKED 'DNP' SHOULD NOT BE POPULATED." at 5532,-918 h60
  text ".VariantName" at 4488,-1034 h60
  text "ASSEMBLY VARIANT:" at 5527,-1034 h60
  text ".VersionControl_RevNumber" at 465.5,-1256.17 h60
  text "SVN REV:" at 971.5,-1256.17 h60
  text ".PCB_Rev" at 1518,-1256.17 h60
  text "REV:" at 1809.5,-1256.17 h60
  text ".PRJ_Number" at 2654,-1256.17 h60
  text "BOARD #:" at 3199.5,-1256.17 h60
  text "PCB VIEWED FROM BOTTOM SIDE" at 5676,-1256.17 h60
  text ".TID" at 2654,-1459.5 h60
  text "TID #:" at 3199.5,-1459.5 h60
  text "TEXAS INSTRUMENTS" at 334.5,-1664.84 h60
  text ".Print_Time" at 1599,-1664.84 h60
  text ".Print_Date" at 2328,-1664.84 h60
  text "GENERATED    :" at 3197.5,-1664.84 h60
  text ".plot_File_Name" at 4870.5,-1664.84 h60
  text "PLOT NAME =" at 5676,-1664.84 h60
M9 Title Sheet:
  drawing of 57 lines, arcs and shapes, not listed
  text "1" at 169.84,7436.5 h70
  text "2" at 2665.5,7436.5 h70
  text "3" at 5154.84,7436.5 h70
  text "4" at 7661.51,7436.5 h70
  text "5" at 10160.5,7436.5 h70
  text "6" at 12665.5,7436.5 h70
  text "A" at -986.5,6293.5 h70
  text "A" at 13813.5,6293.5 h70
  text "B" at -986.5,3913.5 h70
  text "B" at 13813.5,3913.5 h70
  text "C" at -986.5,1538.5 h70
  text "C" at 13813.5,1538.5 h70
  text "PROJECT TITLE:" at 10773.5,-322.5 h45
  text ".PRJ_Title" at 10823.5,-455.83 h125
  text "DESIGNED FOR:" at 10773.5,-623.5 h45
  text ".PRJ_Customer" at 10823.5,-763.5 h125
  text "D" at -986.5,-831.5 h70
  text "D" at 13813.5,-831.5 h70
  text "FILE NAME:" at 10773.5,-923.5 h45
  text ".PCB_File_Name_No_Path" at 10823.5,-1043.5 h125
  text "Texas Instruments (TI) and/or its licensors do not warrant the accuracy or completeness of this specification" at 5804,-1205.34 h45
  text "ENGINEER:" at 10773.5,-1213.5 h45
  text "LAYOUT BY:" at 12278.5,-1213.5 h45
  text "or any information contained therein. TI and/or its licensors do not warrant that this design will meet" at 5759.01,-1318 h45
  text ".PRJ_Engineer" at 10823.5,-1368.49 h125
  text ".PCB_Layout" at 12329,-1368.49 h125
  text "the specifications, will be suitable for your application or fit for any particular purpose, or will operate in" at 5759.01,-1430.67 h45
  text ".Layer_Name" at 7,-1458.49 h60
  text "ALTIUM DESIGNER VERSION:" at 12278.5,-1523.5 h45
  text "an implementation. TI and/or its licensors do not warrant that the design is production worthy. You should" at 5759.01,-1543.33 h45
  text "completely validate and test your design implementation to confirm the system functionality for your application." at 5804,-1656 h45
  text ".print_Scale" at 10823.5,-1656.83 h70
  text ".Application_BuildNumber" at 12329,-1656.83 h70
  text "1" at 169.84,-1863.5 h70
  text "2" at 2665.5,-1863.5 h70
  text "3" at 5154.84,-1863.5 h70
  text "4" at 7661.51,-1863.5 h70
  text "5" at 10160.5,-1863.5 h70
  text "6" at 12665.5,-1863.5 h70
M10 Fab Notes:
  drawing of 173 lines, arcs and shapes, not listed
  text "DESIGN INFORMATION" at 11808.02,5601 h60
  text "MIN. TRACK WIDTH:" at 11163.46,5421 h60
  text "8" at 12259.7,5421 h60
  text "MIL" at 12414.46,5421 h60
  text "MIN. CLEARANCE:" at 11163.46,5289 h60
  text "6" at 12199.7,5289 h60
  text "MIL" at 12414.46,5289 h60
  text "MIN. VIA PAD SIZE:" at 11163.46,5157 h60
  text "22" at 12229.71,5157 h60
  text "MIL" at 12414.46,5157 h60
  text "0.05mm (2MIL)" at 11858.46,5015.29 h60
  text "MINIMUM ANNULAR RING" at 10834.23,5011 h60
  text "EXTERNAL" at 12566.46,5011 h60
  text "PER" at 11034.23,4893 h60
  text "IPC-D-275 CLASS 2 LEVEL C" at 11254.23,4893 h60
  text "MIL, HOLES" at 12742.46,4780.71 h60
  text "+/-" at 12350,4780 h60
  text "+/-" at 13204,4780 h60
  text "REGISTRATION TOLERANCES:" at 10834.23,4775 h60
  text "METAL" at 12034,4775 h60
  text "5" at 12610.2,4775 h60
  text "3" at 13443.2,4775 h60
  text "MIL" at 13559.46,4775 h60
  text "+/-" at 13204,4662 h60
  text "HOLE SIZE TOLERANCE (UNLESS OTHERWISE SPECIFIED):" at 10834.23,4657 h60
  text "3" at 13443.2,4657 h60
  text "MIL" at 13559.46,4657 h60
  text "MATERIAL:" at 10759.46,4447.54 h60
  text "FR-4 High Tg" at 11745.9,4307.21 h60
  text "FR-408" at 11180.46,4298.64 h60
  text "OTHER" at 12668.46,4298.64 h60
  text "X" at 11591,4295 h60
  text "62 MIL (1.6mm) +/-10%" at 11500.56,4135.92 h60
  text "THICKNESS:" at 10834.23,4131.64 h60
  text "X" at 11372.4,4131.64 h60
  text "OTHER" at 12785.46,4131.64 h60
  text "TOLERANCE:" at 10834.23,3973.64 h60
  text "X" at 11673.53,3973.64 h60
  text "ANSI IPC-6012 TYPE 3 CLASS 2" at 11860.48,3973.64 h60
  text "OTHER +/-" at 11860.46,3817.64 h60
  text "BOW & TWIST:" at 10834.23,3660.64 h60
  text "X" at 11673.53,3660.64 h60
  text "ANSI IPC-6012 TYPE 3 CLASS 2" at 11860.48,3660.64 h60
  text "OTHER +/-" at 11860.46,3502.13 h60
  text "DRILLING:" at 10759.46,3363.64 h60
  text "REFERENCE:" at 10834.23,3246.64 h60
  text "X" at 11482.46,3246.64 h60
  text "AS SHOWN" at 11669.46,3246.64 h60
  text "X" at 12383.46,3246.64 h60
  text "NC_DRILL FILES" at 12520.46,3246.64 h60
  text "PTH MIN COPPER THICKNESS:" at 10834.23,3088.64 h60
  text "X" at 12184.46,3088.64 h60
  text "1MIL" at 12321.46,3088.64 h60
  text "OTHER" at 12818.46,3088.64 h60
  text "BOARD FINISH:" at 10759.46,2929.64 h60
  text "SILKSCREEN:" at 10914.68,2811.64 h60
  text "X" at 11863.46,2811.64 h60
  text "TOP" at 11989.46,2811.64 h60
  text "X" at 12373.46,2811.64 h60
  text "BOTTOM" at 12500.46,2811.64 h60
  text "SILKSCREEN COLOR:" at 10914.68,2644.64 h60
  text "X" at 11862.42,2644.64 h60
  text "WHITE" at 11989.46,2644.64 h60
  text "OTHER" at 12500.46,2644.64 h60
  text "X" at 11993.42,2485.44 h60
  text "GREEN" at 12120.46,2485.44 h60
  text "OTHER" at 12738.46,2485.44 h60
  text "SOLDER RESIST COLOR:" at 10914.68,2474.64 h60
  text "X" at 11993.42,2315.44 h60
  text "MATTE" at 12120.46,2315.44 h60
  text "SEMI-GLOSS" at 12738,2314.8 h60
  text "IMMERSION GOLD (ENIG)" at 11820.46,2126.92 h60
  text "ENEPIG" at 13158,2123.64 h60
  text "SURFACE FINISH:" at 10759.46,2122.64 h60
  text "X" at 11633.51,2122.64 h60
  text "IMM. TIN/SILVER OR EQUIV" at 11089,1965.64 h60
  text "OTHER" at 12520.46,1965.64 h60
  text "ARRAY/PANEL:" at 10759.46,1786.64 h60
  text "CUT AND TRIM PER M1 BOARD OUTLINE" at 11820.46,1782.35 h60
  text "N.C. ROUTE" at 11820.46,1630.64 h60
  text "X" at 12499.46,1630.64 h60
  text "V. SCORE" at 12686.46,1630.64 h60
  text "CERTIFICATION:" at 10759.46,1493.64 h60
  text "MATERIALS AND WORKMANSHIP FOR ALL PCBS" at 11484.46,1493.64 h60
  text "TO MEET OR EXCEED THE REQUIREMENTS OF:" at 11484.46,1395.64 h60
  text "X" at 11110.96,1259.13 h60
  text "ANSI IPC-A-600F CLASS ->" at 11249.96,1259.13 h60
  text "X" at 12889.02,1259.13 h60
  text "2" at 13007.96,1259.14 h60
  text "1" at 12692.96,1257.64 h60
  text "3" at 13361.96,1257.64 h60
  text "X" at 11925.02,1099.64 h60
  text "RoHS" at 12061.96,1099.64 h60
  text "OTHER" at 12706.36,1099.64 h60
  text "PER ORDER" at 13103.42,1099.64 h60
  text "ALL BOARDS MUST MEET OR EXCEED UL94-V0 REQUIREMENTS." at 10787,934 h60
  text "PCB MUST BEAR THE UL94V-0 UL REGISTERED MATERIAL ID NUMBER" at 10787,814 h60
  text "ADDITIONAL REQUIREMENTS:" at 10759.46,640.64 h60
  text "MICROSECTION:" at 10834.23,525.64 h60
  text "YES" at 11739.96,525.64 h60
  text "REQUIRED" at 12601.46,369.49 h60
  text "BARE BOARD ELEC. TEST:" at 10834.23,366.64 h60
  text "NONE" at 12139.96,366.64 h60
  text "X" at 12474.46,366.64 h60
  text "PER ORDER" at 13193.46,366.64 h60
  text ".Layer_Name" at 7,-1458.49 h60
M11 Gerber Information:
  lines w10: -862,-1530.17 5738,-1530.17 ; -862,-1326.83 5740,-1326.83 ; -862,-1123.5 -862,-1733.5 3143,-1733.5 5740,-1733.5 5740,-1123.5 -861.5,-1123.5 -861.5,-1733.5 714,-1733.5 ; 1603,-1733.5 1603,-1123.5 ; 2870,-1326.83 2870,-1123.5 ; 3710,-1326.83 3710,-1123.5 ; 4332,-1740 4332,-1537.17
  text "ALL ARTWORK VIEWED FROM TOP SIDE" at -798.5,-1255.67 h60
  text "BOARD #:" at 1678,-1255.67 h60
  text ".PRJ_Number" at 2223.5,-1255.67 h60
  text "REV:" at 3068,-1255.67 h60
  text ".PCB_Rev" at 3359.5,-1255.67 h60
  text "SVN REV:" at 3906,-1255.67 h60
  text ".VersionControl_RevNumber" at 4412,-1255.67 h60
  text "LAYER NAME =" at -798.5,-1458.49 h60
  text "TID #:" at 1678,-1459 h60
  text ".TID" at 2223.5,-1459 h60
  text "PLOT NAME =" at -798.5,-1664.34 h60
  text ".plot_File_Name" at 7,-1664.34 h60
  text "GENERATED    :" at 1680,-1664.34 h60
  text ".Print_Date" at 2549.5,-1664.34 h60
  text ".Print_Time" at 3278.5,-1664.34 h60
  text "TEXAS INSTRUMENTS" at 4543,-1664.34 h60
M12 Stackup:
  drawing of 295 lines, arcs and shapes, not listed
  text "Layer" at 9183.5,7208.5 h60
  text "Name" at 9593.41,7208.5 h60
  text "Material" at 10533.15,7208.5 h60
  text "Thickness" at 11392.92,7208.5 h60
  text "Constant" at 12042.76,7208.5 h60
  text "Board Layer Stack" at 12612.62,7208.5 h60
  text "1" at 9183.5,7088.5 h60
  text "Top Overlay" at 9593.41,7088.5 h60
  text "2" at 9183.5,6968.5 h60
  text "Top Solder" at 9593.41,6968.5 h60
  text "Solder Resist" at 10533.15,6968.5 h60
  text "0.40mil" at 11392.92,6968.5 h60
  text "3.5" at 12042.76,6968.5 h60
  text "3" at 9183.5,6848.5 h60
  text "Top Layer" at 9593.41,6848.5 h60
  text "Copper" at 10533.15,6848.5 h60
  text "1.42mil" at 11392.92,6848.5 h60
  text "4" at 9183.5,6728.5 h60
  text "Dielectric1" at 9593.41,6728.5 h60
  text "FR-4 High TG" at 10533.15,6728.5 h60
  text "10.00mil" at 11392.92,6728.5 h60
  text "4.3" at 12042.76,6728.5 h60
  text "5" at 9183.5,6608.5 h60
  text "Signal Layer 1" at 9593.41,6608.5 h60
  text "Copper" at 10533.15,6608.5 h60
  text "1.42mil" at 11392.92,6608.5 h60
  text "6" at 9183.5,6488.5 h60
  text "Dielectric 3" at 9593.41,6488.5 h60
  text "FR-4 High TG" at 10533.15,6488.5 h60
  text "36.00mil" at 11392.92,6488.5 h60
  text "4.3" at 12042.76,6488.5 h60
  text "7" at 9183.5,6368.5 h60
  text "Signal Layer 2" at 9593.41,6368.5 h60
  text "Copper" at 10533.15,6368.5 h60
  text "1.42mil" at 11392.92,6368.5 h60
  text "8" at 9183.5,6248.5 h60
  text "Dielectric 2" at 9593.41,6248.5 h60
  text "FR-4 High TG" at 10533.15,6248.5 h60
  text "10.00mil" at 11392.92,6248.5 h60
  text "4.3" at 12042.76,6248.5 h60
  text "9" at 9183.5,6128.5 h60
  text "Bottom Layer" at 9593.41,6128.5 h60
  text "Copper" at 10533.15,6128.5 h60
  text "1.42mil" at 11392.92,6128.5 h60
  text "10" at 9183.5,6008.5 h60
  text "Bottom Solder" at 9593.41,6008.5 h60
  text "Solder Resist" at 10533.15,6008.5 h60
  text "0.40mil" at 11392.92,6008.5 h60
  text "3.5" at 12042.76,6008.5 h60
  text "11" at 9183.5,5888.5 h60
  text "Bottom Overlay" at 9593.41,5888.5 h60
  text ".Layer_Name" at 7,-1458.49 h60
M13 Component Bodies Top:
  text ".Layer_Name" at 7,-1458.49 h60
M14 Component Bodies Bottom:
  text ".Layer_Name" at 7,-1458.49 h60
M15 Courtyards Top:
  text ".Layer_Name" at 7,-1458.49 h60
M16 Courtyards Bottom:
  text ".Layer_Name" at 7,-1458.49 h60
Drill Drawing:
  circle w10: c2914.62,5982.17 r16.6
  circle w10: c2914.62,5982.17 r27.67
  circle w10: c2914.62,5733.17 r27.67
  lines w10: 2886.96,5581 2914.62,5594.83 2942.29,5581 2928.46,5608.67 2942.29,5636.33 2914.62,5622.5 2886.96,5636.33 2900.79,5608.67 2886.96,5581 ; 2886.96,5885.33 2942.29,5885.33 2914.62,5830 2886.96,5885.33 ; 2886.96,6079 2886.96,6092.83 2900.79,6106.67 2886.96,6120.5 2886.96,6134.33 2900.79,6134.33 2914.62,6120.5 2928.46,6134.33 2942.29,6134.33 2942.29,6120.5 2928.46,6106.67 2942.29,6092.83 2942.29,6079 2928.46,6079 2914.62,6092.83 2900.79,6079 2886.96,6079 ; 2886.96,6217.33 2900.79,6217.33 2914.62,6203.5 2928.46,6217.33 2942.29,6217.33 2928.46,6231.17 2942.29,6245 2928.46,6245 2914.62,6258.83 2900.79,6245 2886.96,6245 2900.79,6231.17 2886.96,6217.33 ; 2886.96,6328 2942.29,6328 2942.29,6383.33 2886.96,6383.33 2886.96,6328 ; 2886.96,6480.17 2914.62,6452.5 2942.29,6480.17 2914.62,6507.83 2886.96,6480.17 ; 2886.96,6590.83 2900.79,6590.83 2900.79,6577 2928.46,6577 2928.46,6590.83 2942.29,6590.83 2942.29,6618.5 2928.46,6618.5 2928.46,6632.33 2900.79,6632.33 2900.79,6618.5 2886.96,6618.5 2886.96,6590.83 ; 2886.96,6826 2886.96,6839.83 2900.79,6853.67 2886.96,6867.5 2886.96,6881.33 2900.79,6881.33 2914.62,6867.5 2928.46,6881.33 2942.29,6881.33 2942.29,6867.5 2928.46,6853.67 2942.29,6839.83 2942.29,6826 2928.46,6826 2914.62,6839.83 2900.79,6826 2886.96,6826 ; 2886.96,6950.5 2942.29,6950.5 2942.29,7005.83 2886.96,7005.83 2886.96,6950.5 ; 2898.02,5592.07 2914.62,5600.37 2931.23,5592.07 2922.93,5608.67 2931.23,5625.27 2914.62,5616.97 2898.02,5625.27 2906.32,5608.67 2898.02,5592.07 ; 2898.02,6090.07 2898.02,6098.37 2906.32,6106.67 2898.02,6114.97 2898.02,6123.27 2906.32,6123.27 2914.62,6114.97 2922.93,6123.27 2931.23,6123.27 2931.23,6114.97 2922.93,6106.67 2931.23,6098.37 2931.23,6090.07 2922.93,6090.07 2914.62,6098.37 2906.32,6090.07 2898.02,6090.07 ; 2898.02,6339.07 2931.23,6339.07 2931.23,6372.27 2898.02,6372.27 2898.02,6339.07 ; 2898.02,6596.37 2906.32,6596.37 2906.32,6588.07 2922.93,6588.07 2922.93,6596.37 2931.23,6596.37 2931.23,6612.97 2922.93,6612.97 2922.93,6621.27 2906.32,6621.27 2906.32,6612.97 2898.02,6612.97 2898.02,6596.37
  lines w12: 2836.8,5543.65 5914.79,5543.65 ; 2836.8,7037.65 5914.79,7037.65 ; 3174.81,5419.15 3174.81,7162.15 ; 3506.97,5419.15 3506.97,7162.15 ; 4143.45,5419.15 4143.45,7162.15 ; 4402.65,5419.15 4402.65,7162.15 ; 4777.89,5419.15 4777.89,7162.15 ; 5502.44,5419.15 5502.44,7162.15 ; 2836.8,5419.15 5914.79,5419.15 5914.79,7162.15 2836.8,7162.15 2836.8,5419.15
  text "Symbol" at 2911.5,7075 h72
  text "Quantity" at 3212.16,7075 h72
  text "Finished Hole Size" at 3544.32,7075 h72
  text "Plated" at 4180.8,7075 h72
  text "Hole Type" at 4440,7075 h72
  text "Drill Layer Pair" at 4815.24,7075 h72
  text "Tolerance" at 5539.79,7075 h72
  text "8" at 3212.16,6950.5 h60
  text "63.00mil (1.600mm)" at 3544.32,6950.5 h60
  text "NPTH" at 4180.8,6950.5 h60
  text "Round" at 4440,6950.5 h60
  text "Top Layer - Bottom Layer" at 4815.24,6950.5 h60
  text "2" at 3212.16,6826 h60
  text "7.87mil (0.200mm)" at 3544.32,6826 h60
  text "PTH" at 4180.8,6826 h60
  text "Round" at 4440,6826 h60
  text "Top Layer - Bottom Layer" at 4815.24,6826 h60
  text "980" at 3212.16,6701.5 h60
  text "10.00mil (0.254mm)" at 3544.32,6701.5 h60
  text "PTH" at 4180.8,6701.5 h60
  text "Round" at 4440,6701.5 h60
  text "Top Layer - Bottom Layer" at 4815.24,6701.5 h60
  text "A" at 2886.19,6691.51 h55.33
  text "56" at 3212.16,6577 h60
  text "16.00mil (0.406mm)" at 3544.32,6577 h60
  text "PTH" at 4180.8,6577 h60
  text "Round" at 4440,6577 h60
  text "Top Layer - Bottom Layer" at 4815.24,6577 h60
  text "18" at 3212.16,6452.5 h60
  text "19.69mil (0.500mm)" at 3544.32,6452.5 h60
  text "PTH" at 4180.8,6452.5 h60
  text "Round" at 4440,6452.5 h60
  text "Top Layer - Bottom Layer" at 4815.24,6452.5 h60
  text "6" at 3212.16,6328 h60
  text "26.00mil (0.660mm)" at 3544.32,6328 h60
  text "PTH" at 4180.8,6328 h60
  text "Round" at 4440,6328 h60
  text "Top Layer - Bottom Layer" at 4815.24,6328 h60
  text "4" at 3212.16,6203.5 h60
  text "40.16mil (1.020mm)" at 3544.32,6203.5 h60
  text "PTH" at 4180.8,6203.5 h60
  text "Round" at 4440,6203.5 h60
  text "Top Layer - Bottom Layer" at 4815.24,6203.5 h60
  text "16" at 3212.16,6079 h60
  text "47.24mil (1.200mm)" at 3544.32,6079 h60
  text "PTH" at 4180.8,6079 h60
  text "Round" at 4440,6079 h60
  text "Top Layer - Bottom Layer" at 4815.24,6079 h60
  text "2" at 3212.16,5954.5 h60
  text "51.18mil (1.300mm)" at 3544.32,5954.5 h60
  text "PTH" at 4180.8,5954.5 h60
  text "Round" at 4440,5954.5 h60
  text "Top Layer - Bottom Layer" at 4815.24,5954.5 h60
  text "2" at 3212.16,5830 h60
  text "63.00mil (1.600mm)" at 3544.32,5830 h60
  text "PTH" at 4180.8,5830 h60
  text "Round" at 4440,5830 h60
  text "Top Layer - Bottom Layer" at 4815.24,5830 h60
  text "3" at 3212.16,5705.5 h60
  text "137.80mil (3.500mm)" at 3544.32,5705.5 h60
  text "PTH" at 4180.8,5705.5 h60
  text "Round" at 4440,5705.5 h60
  text "Top Layer - Bottom Layer" at 4815.24,5705.5 h60
  text "2" at 3212.16,5581 h60
  text "188.00mil (4.775mm)" at 3544.32,5581 h60
  text "PTH" at 4180.8,5581 h60
  text "Round" at 4440,5581 h60
  text "Top Layer - Bottom Layer" at 4815.24,5581 h60
  text "1099 Total" at 3212.16,5456.5 h60
  text ".Layer_Name" at 7,-1458.49 h60

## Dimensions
0,0 to 928.92,-500.33 on M2 Board Dimensions
0,0 to 2274,3278 on M2 Board Dimensions
0,0 to 2274,1738 on M2 Board Dimensions
0,0 to 2274,246 on M2 Board Dimensions
929,-137 to 2274,246 on M2 Board Dimensions
0,0 to 929,-138 on M2 Board Dimensions
0,0 to 2274,246 on M2 Board Dimensions
0,0 to 0,4500 on M2 Board Dimensions
0,0 to 5700,0 on M2 Board Dimensions
1080,0 to 4500,0 on M3 3D STEP Top
-220,-1000 to 780,-1000 on M2 Board Dimensions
